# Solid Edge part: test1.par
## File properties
Author: CADCIM
Template: Normal.par
Last saved by: TIET
Revision: 4
Application: Solid Edge
Accuracy: 0.99
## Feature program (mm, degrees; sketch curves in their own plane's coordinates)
sketch for "unnamed Protrusion 1" #1 plane through (0, 0, 0) normal (0, 0, 1) x-axis (1, 0, 0)
  line (-47.52, 0) -> (-47.52, 46.944)
  line (-47.52, 46.944) -> (47.52, 46.944)
  line (47.52, 46.944) -> (47.52, 0)
  line (47.52, 0) -> (-47.52, 0)
sketch for "unnamed Protrusion 1" #2 plane through (0, 0, 0) normal (0, 0, 1) x-axis (1, 0, 0)
  circle centre (-33.4173, 33.1293) radius 7.1111
sketch for "unnamed Protrusion 1" #3 plane through (0, 0, 0) normal (0, 0, 1) x-axis (1, 0, 0)
  circle centre (0, 13.2015) radius 7.2161
sketch for "unnamed Protrusion 1" #4 plane through (0, 0, 0) normal (0, 0, 1) x-axis (1, 0, 0)
  circle centre (36.4831, 33.1293) radius 6.1622
extrude "unnamed Protrusion 1" add finite 6.35 along +normal
sketch for "ExtrudedProtrusion_2" #1 plane through (0, 23.472, 6.35) normal (0, 0, 1) x-axis (0, 1, 0)
sketch for "ExtrudedProtrusion_2" #2 plane through (0, 23.472, 6.35) normal (0, 0, 1) x-axis (0, 1, 0)
sketch for "ExtrudedProtrusion_2" #3 plane through (0, 23.472, 6.35) normal (0, 0, 1) x-axis (0, 1, 0)
  circle centre (-10.2705, 0) radius 7.2161
extrude "ExtrudedProtrusion_2" add finite 28.575 along -normal
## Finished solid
Body 1: solid body, 12 faces, 18 edges, 8 vertices.
  Faces by surface: plane 9, cylinder 3
  Edges by curve: line 12, circle 6
Bounding box of the edges (mm): 95.040 x 46.944 x 28.575, from (-47.52, 0, -22.225) to (47.52, 46.944, 6.35).
Cylindrical faces by radius (mm): R6.1622 x1, R7.1111 x1, R7.2161 x1
Planar faces by outward normal: +x 1, +y 1, +z 1, -x 1, -y 1, -z 4
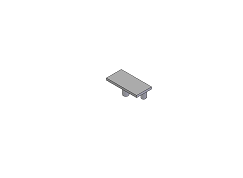
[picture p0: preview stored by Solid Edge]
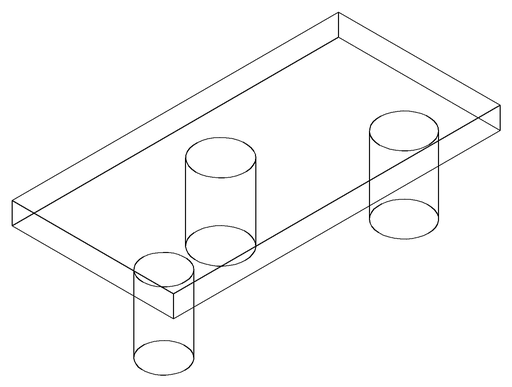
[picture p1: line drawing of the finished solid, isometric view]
